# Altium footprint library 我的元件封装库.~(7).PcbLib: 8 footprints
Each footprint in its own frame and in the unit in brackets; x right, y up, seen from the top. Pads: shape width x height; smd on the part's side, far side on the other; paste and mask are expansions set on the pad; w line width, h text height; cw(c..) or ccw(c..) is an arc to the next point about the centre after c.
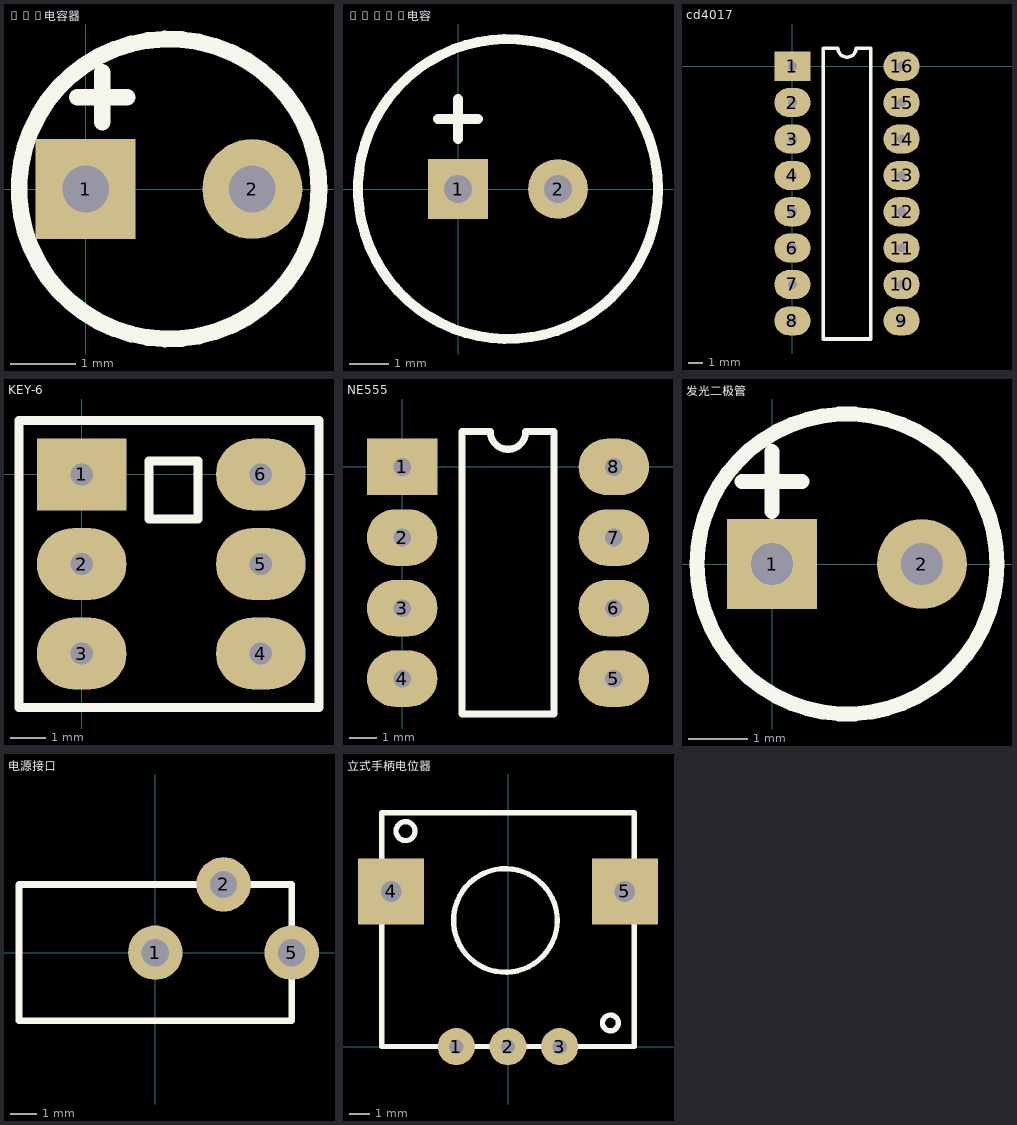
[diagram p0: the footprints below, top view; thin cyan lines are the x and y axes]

## 1uF电容器 [mil]
pads (2):
  rect 60x60 hole 28: 1(0,0)
  round 60 hole 28: 2(100,0)
Top Overlay:
  circle w10: c50,0 r90
  lines w10: -5,55 25,55 ; 10,40 10,70

## 220uF电容 [mil]
pads (2):
  rect 60x60 hole 28: 1(0,0)
  round 60 hole 28: 2(100,0)
Top Overlay:
  circle w10: c50,0 r150
  lines w10: -20,70 20,70 ; 0,50 0,90

## cd4017 [mil]
pads (16):
  rect 100x80 hole 25: 1(0,0)
  oval 100x80 hole 25: 2(0,-100) 3(0,-200) 4(0,-300) 5(0,-400) 6(0,-500) 7(0,-600) 8(0,-700) 9(300,-700) 10(300,-600) 11(300,-500) 12(300,-400) 13(300,-300) 14(300,-200) 15(300,-100) 16(300,0)
Top Overlay:
  lines w10: 85,-750 85,50 125,50 ccw(c150,50) 175,50 215,50 215,-750 85,-750

## KEY-6 [mil]
pads (6):
  rect 100x80 hole 25: 1(0,0)
  oval 100x80 hole 25: 2(0,-100) 3(0,-200) 4(200,-200) 5(200,-100) 6(200,0)
Top Overlay:
  lines w10: -70,-260 -70,60 265,60 265,-260 -70,-260 ; 75,-50 130,-50 130,15 75,15 75,-50

## NE555 [mil]
pads (8):
  rect 100x80 hole 25: 1(0,0)
  oval 100x80 hole 25: 2(0,-100) 3(0,-200) 4(0,-300) 5(300,-300) 6(300,-200) 7(300,-100) 8(300,0)
Top Overlay:
  lines w10: 85,-350 85,50 125,50 ccw(c150,50) 175,50 215,50 215,-350 85,-350

## 发光二极管 [mil]
pads (2):
  rect 60x60 hole 28: 1(0,0)
  round 60 hole 28: 2(100,0)
Top Overlay:
  circle w10: c50,0 r100
  lines w10: -20,55 20,55 ; 0,35 0,75

## 电源接口 [mil]
pads (3):
  round 80 hole 40: 1(0,0) 2(100,100) 5(200,0)
Top Overlay:
  lines w10: -200,-100 200,-100 200,100 -200,100 -200,-100

## 立式手柄电位器 [mm]
pads (5):
  round 1.8 hole 0.7 square: 1(-2.5,0) 2(0,0) 3(2.5,0)
  rect 3.2x3.2 hole 1 square: 4(-5.65,7.5) 5(5.65,7.5)
Top Overlay:
  circle w0.254: c4.953,1.143 r0.381
  circle w0.254: c-4.953,10.414 r0.458
  circle w0.254: c-0.127,6.096 r2.505
  lines w0.254: 6.096,2.032 6.1,2.028 ; -6.1,0 -6.1,11.3 6.1,11.3 6.1,0 -6.1,0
